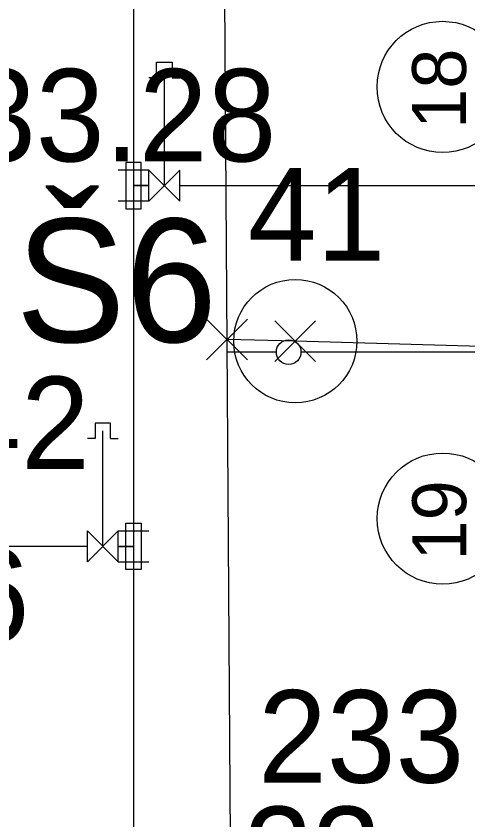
# Model space of a CAD drawing. Extents: x -264031 to -263588, y -1242281 to -1242059.
# Drawn here: x -263926.05 to -263918.71, y -1242207.77 to -1242194.73 of the extents above; entities that cross this region are included whole.
import ezdxf

# ---------------------------------------------------------------- set-up
doc = ezdxf.new("R2010")
doc.units = 0
for name, color, linetype in [('HESCON_OSI_STAVBY_KFA', 7, 'Continuous'), ('KFA_2D_SITUACIA_DSP', 7, 'Continuous'), ('KFA_BODY_CISLO', 7, 'Continuous'), ('KFA_BODY_SYMBOL', 7, 'Continuous'), ('KFA_BODY_VYSKA', 7, 'Continuous'), ('KFA_JESTV_IS_DSP_-_KANAL_SPLASK', 7, 'Continuous'), ('KFA_SO-40-1-II_SK_MER_TRIBUNA_A', 7, 'Continuous'), ('POPIS', 7, 'Continuous')]:
    doc.layers.add(name, color=color, linetype=linetype)

msp = doc.modelspace()

# ---------------------------------------------------------------- linework, layer by layer
at = {"layer": 'HESCON_OSI_STAVBY_KFA'}
for centre in [(-263919.125, -1242195.882), (-263919.123, -1242202.882)]:
    msp.add_circle(centre, 1.064, dxfattribs=at)
at = {"layer": 'KFA_2D_SITUACIA_DSP'}
for p, q in [((-263924.143, -1242185.14), (-263924.143, -1242250.14)), ((-263923.768, -1242195.732), (-263923.768, -1242195.482)), ((-263923.768, -1242195.482), (-263923.518, -1242195.482)), ((-263923.518, -1242195.482), (-263923.518, -1242195.732)), ((-263923.643, -1242197.482), (-263923.643, -1242195.607)), ((-263923.768, -1242195.732), (-263923.893, -1242195.732)), ((-263923.518, -1242195.732), (-263923.393, -1242195.732)), ((-263924.018, -1242197.107), (-263924.268, -1242197.107)), ((-263924.268, -1242197.107), (-263924.268, -1242197.857)), ((-263924.018, -1242197.857), (-263924.018, -1242197.107)), ((-263923.893, -1242197.232), (-263924.393, -1242197.232)), ((-263923.893, -1242197.732), (-263923.893, -1242197.232)), ((-263923.893, -1242197.232), (-263923.393, -1242197.732)), ((-263923.393, -1242197.232), (-263923.893, -1242197.732)), ((-263923.393, -1242197.732), (-263923.393, -1242197.232)), ((-263924.143, -1242197.482), (-263923.893, -1242197.482)), ((-263923.893, -1242197.482), (-263924.143, -1242197.482)), ((-263923.393, -1242197.482), (-263915.293, -1242197.482)), ((-263923.893, -1242197.732), (-263924.393, -1242197.732)), ((-263924.268, -1242197.857), (-263924.018, -1242197.857)), ((-263921.824, -1242200.182), (-263922.624, -1242200.182)), ((-263915.293, -1242200.182), (-263921.424, -1242200.182)), ((-263924.768, -1242201.332), (-263924.768, -1242201.582)), ((-263924.518, -1242201.332), (-263924.768, -1242201.332)), ((-263924.518, -1242201.582), (-263924.518, -1242201.332)), ((-263924.643, -1242203.332), (-263924.643, -1242201.457)), ((-263924.768, -1242201.582), (-263924.893, -1242201.582)), ((-263924.518, -1242201.582), (-263924.393, -1242201.582)), ((-263924.268, -1242203.707), (-263924.268, -1242202.957)), ((-263924.268, -1242202.957), (-263924.018, -1242202.957)), ((-263924.018, -1242202.957), (-263924.018, -1242203.707)), ((-263924.893, -1242203.582), (-263924.893, -1242203.082)), ((-263924.393, -1242203.082), (-263924.893, -1242203.582)), ((-263924.893, -1242203.082), (-263924.393, -1242203.582)), ((-263924.393, -1242203.582), (-263924.393, -1242203.082)), ((-263924.393, -1242203.082), (-263923.893, -1242203.082)), ((-263924.893, -1242203.332), (-263958.097, -1242203.332)), ((-263924.143, -1242203.332), (-263924.393, -1242203.332)), ((-263924.393, -1242203.332), (-263924.143, -1242203.332)), ((-263924.393, -1242203.582), (-263923.893, -1242203.582)), ((-263924.018, -1242203.707), (-263924.268, -1242203.707))]:
    msp.add_line(p, q, dxfattribs=at)
msp.add_circle((-263921.624, -1242200.182), 0.2, dxfattribs=at)
at = {"layer": 'KFA_BODY_SYMBOL'}
for p, q in [((-263922.957, -1242200.309), (-263922.294, -1242199.647)), ((-263922.294, -1242200.309), (-263922.957, -1242199.647)), ((-263921.849, -1242200.336), (-263921.186, -1242199.673)), ((-263921.186, -1242200.336), (-263921.849, -1242199.673))]:
    msp.add_line(p, q, dxfattribs=at)
at = {"layer": 'KFA_JESTV_IS_DSP_-_KANAL_SPLASK'}
msp.add_line((-263922.479, -1242221.753), (-263922.731, -1242184.174), dxfattribs=at)
at = {"layer": 'KFA_SO-40-1-II_SK_MER_TRIBUNA_A'}
msp.add_lwpolyline([(-263915.293, -1242200.182), (-263921.517, -1242200.004), (-263922.625, -1242199.978)], dxfattribs=at)
msp.add_circle((-263921.517, -1242200.004), 1, dxfattribs=at)

# ---------------------------------------------------------------- texts
at = {"layer": 'HESCON_OSI_STAVBY_KFA'}
for s, p in [('18', (-263918.744, -1242196.562)), ('19', (-263918.742, -1242203.562))]:
    msp.add_text(s, height=0.875, rotation=90, dxfattribs=at).set_placement(p)
at = {"layer": 'KFA_BODY_CISLO'}
for s, p in [('41', (-263922.286, -1242198.698)), ('42', (-263927.085, -1242202.079)), ('23', (-263922.354, -1242209.052))]:
    msp.add_text(s, height=1.5, dxfattribs=at).set_placement(p)
at = {"layer": 'KFA_BODY_VYSKA'}
for s, p in [('233.28', (-263927.96, -1242197.09)), ('233.26', (-263931.968, -1242204.877)), ('233.42', (-263922.12, -1242207.164))]:
    msp.add_text(s, height=1.5, dxfattribs=at).set_placement(p)
at = {"layer": 'POPIS'}
msp.add_text('Š6', height=2, dxfattribs=at).set_placement((-263926.057, -1242200.019))

doc.saveas('drawing.dxf')
